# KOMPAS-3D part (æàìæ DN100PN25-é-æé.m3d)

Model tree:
1. Объединить компоненты:1  (labels: СЕНС DN100PN25-В)
2. Эскиз:1
3. Операция выдавливания:1
     Расстояние 1 = 14
4. Фаска:1
     Угол = 45; Длина 1 = 2; Длина 2 = 2

Referenced files in D:\Савин\!СЕНСОР\3D для заказчика\!Новый перечень\СЕНС\3. СЕНС-В\DN100\: СЕНС DN100PN25-В.a3d
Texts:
  СЕНС DN100PN25-В-СВ
  ООО НПП Сенсор
  СЕНС DN100PN25-В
